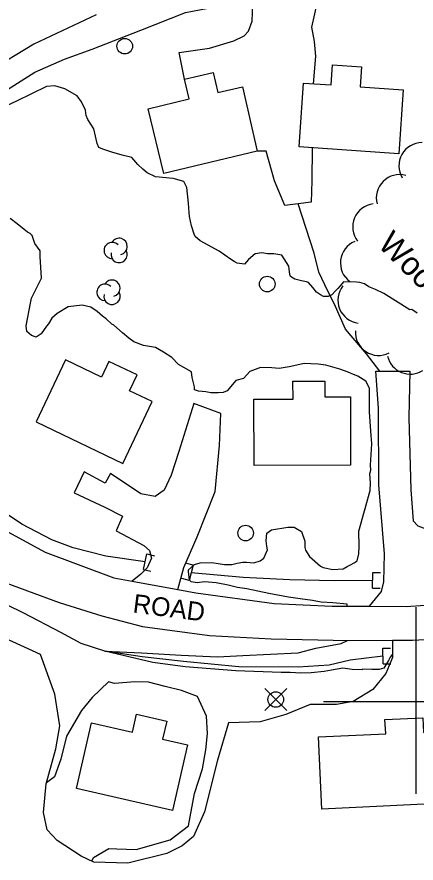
# Model space of a CAD drawing. Extents: x 642515 to 647219, y 6080136 to 6084356.
# Drawn here: x 643548.7 to 643600, y 6081979.3 to 6082088.1 of the extents above; entities that cross this region are included whole.
import ezdxf

# ---------------------------------------------------------------- set-up
doc = ezdxf.new("R2010")
doc.units = 0
for name, color, linetype in [('Level 1', 7, 'Continuous'), ('Level 19', 7, 'Continuous'), ('Level 2', 7, 'Continuous'), ('Level 21', 7, 'Continuous'), ('Level 22', 7, 'Continuous'), ('Level 26', 7, 'Continuous'), ('Level 31', 7, 'Continuous'), ('Level 36', 7, 'Continuous'), ('Level 4', 7, 'Continuous'), ('Level 44', 7, 'Continuous'), ('Level 61', 7, 'Continuous')]:
    doc.layers.add(name, color=color, linetype=linetype)

msp = doc.modelspace()

# ---------------------------------------------------------------- linework, layer by layer
at = {"layer": 'Level 1'}
msp.add_lwpolyline([(643558.37, 6081979.52), (643558.6, 6081980), (643560.55, 6081981.13), (643561.59, 6081981.11), (643564.08, 6081981), (643568.42, 6081982.26), (643570.81, 6081984.06), (643571.56, 6081988.22), (643572.59, 6081991.37), (643573.02, 6081993.85), (643573.23, 6081995.93), (643573.12, 6081998.14), (643571.94, 6082000.7), (643569.89, 6082001.46), (643567.78, 6082001.99), (643565.67, 6082002.51), (643563.9, 6082002.58), (643561.27, 6082002.36), (643560.53, 6082002.56), (643558.39, 6082000.54), (643557.04, 6081998.88), (643555.13, 6081995.61), (643554.4, 6081992.63), (643553.56, 6081990.37), (643552.52, 6081989.61)], dxfattribs=at)
at = {"layer": 'Level 19'}
for points in [[(643588.19, 6082093.13), (643587.38, 6082090.18), (643586.61, 6082086.74), (643586.95, 6082084.9), (643587.1, 6082083.01), (643586.8, 6082079.46)], [(643570.27, 6082080.03), (643569.59, 6082083.48), (643573.48, 6082084.04), (643576.63, 6082084.97), (643577.97, 6082085.61), (643578.5, 6082086.2), (643578.99, 6082087.52), (643579.07, 6082089.75), (643578.61, 6082092.74)], [(643586.69, 6082071.22), (643586.65, 6082066.97), (643586.56, 6082064.22), (643584.91, 6082064.02), (643583.19, 6082063.8), (643581.87, 6082066.97), (643580.77, 6082070.79), (643579.62, 6082070.81)], [(643594.06, 6082012.28), (643595.6, 6082014.17), (643595.89, 6082015.44), (643595.97, 6082019.03), (643595.27, 6082027.89), (643595.23, 6082037.77), (643594.88, 6082042.5), (643595.38, 6082042.5), (643599.24, 6082042.49), (643599.13, 6082036.56), (643599.38, 6082027.26), (643599.69, 6082023.25), (643600.29, 6082022.63), (643601.78, 6082022.06), (643602.53, 6082022.31), (643606.27, 6082024.68), (643612.18, 6082028.17), (643615.8, 6082030.58), (643617.11, 6082032.38), (643618.45, 6082034.47), (643620.21, 6082036.86), (643621.38, 6082039.02), (643621.98, 6082040.21)], [(643569.41, 6082014.44), (643570.18, 6082017.26), (643571.89, 6082021.22), (643574.22, 6082027.06), (643574.77, 6082032.97), (643574.94, 6082037.09), (643571.47, 6082038.36), (643569.53, 6082032.17), (643568.57, 6082029.14), (643567.67, 6082027.2), (643566.5, 6082026.41), (643564.67, 6082026.76), (643560.77, 6082029.34), (643560.07, 6082028.13), (643557.37, 6082029.56), (643556.11, 6082026.88), (643560.05, 6082025.03), (643562.29, 6082023.86), (643561.51, 6082021.97), (643565.05, 6082020.1), (643565.77, 6082019.45), (643566.03, 6082018.46), (643565.46, 6082017.22), (643564.66, 6082016.41), (643563.54, 6082015.5)], [(643597.01, 6082007.92), (643597.02, 6082005.7), (643596.17, 6082003.64), (643594.47, 6082001.58), (643591.94, 6082000.04), (643589.82, 6081999.65), (643586.44, 6081999.64), (643583.32, 6081998.39), (643579.99, 6081997.41), (643575.93, 6081997.32), (643574.51, 6081992.5), (643572.83, 6081985.86), (643571.44, 6081982.69), (643569.98, 6081981.49), (643568.02, 6081980.5), (643563.01, 6081979.27), (643558.61, 6081979.41), (643557, 6081980.17), (643553.9, 6081982.18), (643552.61, 6081983.56), (643552.16, 6081985.78), (643552.48, 6081989.46), (643553.75, 6081993.95), (643554.26, 6081996.91), (643553.63, 6082000.98), (643551.76, 6082006.07), (643543.57, 6082009.83)]]:
    msp.add_lwpolyline(points, dxfattribs=at)
at = {"layer": 'Level 2'}
for points in [[(643552.53, 6082079.09), (643548.68, 6082077.22), (643547.39, 6082076.63), (643545.2, 6082075.4), (643544.2, 6082075.14), (643543.39, 6082074.58), (643540.62, 6082072.8), (643539.44, 6082072.66), (643540.36, 6082074.19), (643542.27, 6082076.96), (643543.27, 6082077.89), (643544.92, 6082079.46), (643545.23, 6082079.63), (643545.86, 6082081.5)], [(643600.17, 6082049.97), (643599.5, 6082050.42), (643599.26, 6082050.4), (643595.89, 6082052.5), (643594.82, 6082053), (643593.99, 6082053.35), (643593.41, 6082053.72), (643592.83, 6082053.93), (643592.39, 6082053.95), (643590.74, 6082053.98), (643590.55, 6082053.77), (643590.28, 6082053.48), (643589.98, 6082053.14), (643589.71, 6082052.85), (643589.22, 6082052.31), (643588.74, 6082052.12), (643588.14, 6082052.13), (643587.77, 6082052.31), (643587.26, 6082052.68), (643586.79, 6082053.25), (643586.23, 6082053.9), (643585.95, 6082054.01), (643585.3, 6082054.13), (643584.48, 6082054.33), (643584.23, 6082054.48), (643583.9, 6082054.7), (643583.8, 6082054.93), (643583.71, 6082056), (643582.79, 6082057.43), (643581.77, 6082057.58), (643580.97, 6082057.61), (643580.24, 6082057.73), (643579.36, 6082057.61), (643578.51, 6082056.85), (643577.98, 6082056.26), (643577.04, 6082056.41), (643576.67, 6082056.59), (643576.21, 6082056.92), (643574.75, 6082057.92), (643572.3, 6082059.27), (643571.67, 6082059.84), (643571.54, 6082060.11), (643571.16, 6082061.2), (643570.93, 6082062.39), (643570.86, 6082062.9), (643570.8, 6082064.1), (643570.57, 6082066.12), (643570.21, 6082066.9), (643568.82, 6082067.3), (643566.55, 6082067.5), (643565.48, 6082068.01), (643564.93, 6082068.5), (643564.3, 6082069.06), (643563.52, 6082069.98), (643562.26, 6082070.27), (643560.95, 6082070.68), (643559.76, 6082071.06), (643559.27, 6082071.27), (643559.04, 6082071.78), (643558.83, 6082072.72), (643558.62, 6082073.67), (643557.87, 6082074.87), (643557.64, 6082075.37), (643557.57, 6082076.05), (643557.02, 6082077.14), (643556.5, 6082077.91), (643554.88, 6082078.82), (643553.61, 6082079.19), (643552.53, 6082079.09)], [(643584.7, 6082043.29), (643583.75, 6082043.08), (643582.47, 6082042.86), (643581.5, 6082042.96), (643580.06, 6082042.97), (643578.68, 6082042.46), (643577.88, 6082041.58), (643576.89, 6082041.33), (643575.75, 6082039.99), (643575.24, 6082039.77), (643574.6, 6082039.73), (643574.12, 6082039.71), (643573.68, 6082039.73), (643573.03, 6082039.85), (643572.06, 6082039.96), (643571.57, 6082040.09), (643571.55, 6082040.49), (643571.28, 6082041.71), (643571.16, 6082042.42), (643570.21, 6082042.97), (643569.51, 6082043.37), (643568.65, 6082044.28), (643567.57, 6082044.94), (643566.54, 6082045.56), (643565, 6082045.8), (643563.76, 6082046.29), (643563.14, 6082046.77), (643562.3, 6082047.44), (643561.2, 6082048.42), (643560.95, 6082048.57), (643560.19, 6082049.24), (643559.73, 6082049.58), (643559.06, 6082050.18), (643558.26, 6082050.73), (643557.13, 6082050.99), (643555.33, 6082050.78), (643553.93, 6082049.91), (643553.24, 6082049.32), (643552.79, 6082048.58), (643552.53, 6082048.28), (643551.86, 6082047.29), (643551.19, 6082046.9), (643550.62, 6082047.11), (643549.99, 6082047.59), (643549.91, 6082048.34), (643550.48, 6082051.24), (643550.61, 6082051.88), (643551.88, 6082054.46), (643551.73, 6082057.24), (643551.73, 6082057.99), (643551.04, 6082058.91), (643550.7, 6082059.97), (643550.45, 6082060.2), (643550.08, 6082060.38), (643548.77, 6082061.46), (643547.85, 6082062.13)], [(643591.21, 6082012.3), (643591.18, 6082012.57), (643589.36, 6082012.75), (643587.83, 6082012.83), (643586.73, 6082013.05), (643585.15, 6082013.24), (643583.66, 6082013.44), (643581.14, 6082013.95), (643579.72, 6082014.23), (643578.3, 6082014.51), (643577.09, 6082014.69), (643575.9, 6082014.98), (643574.36, 6082015.3), (643572.87, 6082015.42), (643571.91, 6082015.29), (643571.14, 6082015.45), (643570.93, 6082015.63), (643570.79, 6082016.74), (643570.78, 6082016.98), (643571.55, 6082017.65), (643572.3, 6082017.89), (643573.78, 6082017.93), (643575.44, 6082017.66), (643576.37, 6082017.67), (643577.04, 6082017.82), (643577.76, 6082017.94), (643578.24, 6082017.97), (643579.21, 6082017.86), (643580, 6082018.14), (643580.46, 6082018.48), (643580.97, 6082019.54), (643580.86, 6082020.01), (643580.79, 6082020.69), (643580.85, 6082021.68), (643581.47, 6082022.12), (643583.55, 6082022.46), (643584.39, 6082022.47), (643585.3, 6082021.88), (643585.73, 6082020.67), (643585.73, 6082019.83), (643585.83, 6082019.52), (643586.36, 6082018.67), (643587.75, 6082017.43), (643588.12, 6082017.26), (643589.34, 6082017), (643590.66, 6082017.11), (643591.2, 6082017.38), (643591.63, 6082017.6), (643592.1, 6082017.86), (643592.49, 6082018.12), (643592.68, 6082019.01), (643592.75, 6082020.01), (643592.69, 6082021.95), (643594.15, 6082027.16), (643594.21, 6082028.16), (643594.11, 6082029.3), (643594.25, 6082029.79), (643594.21, 6082030.42), (643594.35, 6082033.18), (643594.23, 6082034.8), (643594.06, 6082037.3), (643594.06, 6082040.32), (643593.57, 6082041.21), (643592.57, 6082041.88), (643592, 6082042.08), (643591.3, 6082042.4), (643590.23, 6082042.75), (643589.33, 6082043.02), (643588.44, 6082043.29), (643587.47, 6082043.4), (643586.54, 6082043.47), (643585.65, 6082043.5), (643584.7, 6082043.29)], [(643597.02, 6082006.12), (643596.71, 6082005.73), (643596.49, 6082005.32), (643595.9, 6082004.33), (643595.3, 6082004.18), (643594.38, 6082004.17), (643593.17, 6082004.19), (643593.1, 6082004.11), (643591.85, 6082004.16), (643590.64, 6082004.34), (643589.16, 6082004.06), (643588.25, 6082003.89), (643586.57, 6082003.72), (643585.25, 6082003.69), (643583.88, 6082003.78), (643582.71, 6082003.76), (643576.88, 6082003.97), (643570.35, 6082004.5), (643566.22, 6082005.07), (643560.04, 6082006.51), (643564.75, 6082006.32), (643569.87, 6082006), (643574.54, 6082005.77), (643577.79, 6082005.98), (643584.88, 6082006.31), (643587.17, 6082006.91), (643590.44, 6082007.48), (643591.24, 6082007.88)]]:
    msp.add_lwpolyline(points, dxfattribs=at)
at = {"layer": 'Level 21'}
for points in [[(643558.93, 6082088.3), (643550.89, 6082084.56), (643545.1, 6082081.03)], [(643547.58, 6082021.86), (643552.37, 6082019.25), (643561.19, 6082015.93), (643563.54, 6082015.5), (643569.41, 6082014.44), (643571.75, 6082014.02), (643581.8, 6082012.65), (643589.25, 6082012.31), (643594.06, 6082012.28), (643598.78, 6082012.24), (643601.23, 6082012.43)], [(643545.63, 6082015.92), (643554.17, 6082012.78), (643559.67, 6082011.05), (643564.87, 6082009.67), (643573.49, 6082008.51), (643581.43, 6082008.12), (643591.41, 6082007.87), (643597.01, 6082007.92), (643599.6, 6082007.94), (643605.23, 6082008.23)]]:
    msp.add_lwpolyline(points, dxfattribs=at)
at = {"layer": 'Level 22'}
msp.add_lwpolyline([(643595.38, 6082042.5), (643593.69, 6082044.76), (643590.99, 6082047.93), (643589.53, 6082051.2), (643588.69, 6082052.79), (643587.55, 6082055.24), (643586.94, 6082057.68), (643584.91, 6082064.02)], dxfattribs=at)
at = {"layer": 'Level 26'}
for p, q in [((643564.99, 6082017.03), (643565.43, 6082019.01)), ((643565.43, 6082019.01), (643566.41, 6082018.79)), ((643564.99, 6082017.03), (643565.97, 6082016.81)), ((643571.38, 6082017.55), (643570.42, 6082017.81)), ((643571.38, 6082017.55), (643570.88, 6082015.61)), ((643570.88, 6082015.61), (643569.92, 6082015.85)), ((643594.44, 6082014.62), (643594.48, 6082016.64)), ((643594.48, 6082016.64), (643595.48, 6082016.62)), ((643594.44, 6082014.62), (643595.44, 6082014.6)), ((643595.76, 6082006.89), (643596.76, 6082006.91)), ((643595.8, 6082004.87), (643595.76, 6082006.89)), ((643595.8, 6082004.87), (643596.8, 6082004.89))]:
    msp.add_line(p, q, dxfattribs=at)
at = {"layer": 'Level 31'}
for points in [[(643597.84, 6082070.45), (643585.01, 6082071.33), (643585.58, 6082079.54), (643589.12, 6082079.3), (643589.3, 6082081.91), (643593.02, 6082081.65), (643592.84, 6082079.07), (643598.37, 6082078.69), (643597.84, 6082070.45)], [(643579.62, 6082070.81), (643567.62, 6082067.91), (643565.61, 6082076.24), (643570.88, 6082077.52), (643570.27, 6082080.03), (643573.95, 6082080.92), (643574.58, 6082078.32), (643577.73, 6082079.08), (643579.62, 6082070.81)], [(643563.22, 6082039.98), (643564.2, 6082042.02), (643560.56, 6082043.76), (643559.6, 6082041.76), (643555, 6082043.96), (643551.19, 6082035.99), (643562.34, 6082030.66), (643566.13, 6082038.59), (643563.22, 6082039.98)], [(643591.61, 6082030.42), (643579.22, 6082030.38), (643579.19, 6082038.9), (643584.23, 6082038.92), (643584.22, 6082041.21), (643588.31, 6082041.22), (643588.31, 6082039.19), (643591.63, 6082039.2), (643591.61, 6082030.42)], [(643615.11, 6081987.55), (643587.95, 6081986.22), (643587.5, 6081995.49), (643596.14, 6081995.91), (643596.05, 6081997.71), (643600.93, 6081997.95), (643601.02, 6081996.08), (643606.72, 6081996.36), (643606.62, 6081998.26), (643611.34, 6081998.49), (643611.43, 6081996.64), (643614.72, 6081996.8), (643615.11, 6081987.55)], [(643570.66, 6081994.47), (643568.72, 6081986.03), (643556.39, 6081988.85), (643558.32, 6081997.29), (643563.58, 6081996.09), (643564.11, 6081998.41), (643567.99, 6081997.53), (643567.46, 6081995.19), (643570.66, 6081994.47)]]:
    msp.add_lwpolyline(points, dxfattribs=at)
at = {"layer": 'Level 36'}
for p, q in [((643583.42, 6081998.89), (643580.6, 6082001.71)), ((643580.6, 6081998.89), (643583.42, 6082001.71))]:
    msp.add_line(p, q, dxfattribs=at)
for centre in [(643562.6, 6082084.29), (643580.92, 6082053.71), (643578.14, 6082021.7), (643582.01, 6082000.3)]:
    msp.add_circle(centre, 1, dxfattribs=at)
at = {"layer": 'Level 4'}
for points in [[(643526.43, 6082037.47), (643521.14, 6082040.98), (643518.78, 6082042.55), (643517.96, 6082043.51), (643517.75, 6082044.39), (643518.06, 6082046.1), (643519.15, 6082048.17), (643521.07, 6082050.57), (643524.53, 6082056.39), (643528.11, 6082060.81), (643532.77, 6082066.18), (643536.28, 6082069.83), (643539.44, 6082072.66), (643543.44, 6082075.5), (643546.57, 6082078.12), (643551.02, 6082080.94), (643554.85, 6082082.64), (643558.39, 6082083.91), (643564.65, 6082086.34), (643570.39, 6082088.62), (643574, 6082089.3), (643577.08, 6082089.79)], [(643565.21, 6082018.01), (643560.16, 6082018.71), (643555.98, 6082019.79), (643553.22, 6082020.81), (643549.35, 6082022.83), (643545.94, 6082025.11), (643539.87, 6082028.86), (643534.05, 6082032.47), (643531.59, 6082034.07)], [(643595.78, 6082005.87), (643591.56, 6082005.37), (643588.89, 6082004.71), (643584.91, 6082004.46), (643577.28, 6082004.51), (643570.13, 6082005.18), (643564.85, 6082005.79), (643560.04, 6082006.51), (643557, 6082007.48), (643554.38, 6082008.91), (643549.63, 6082011.41), (643542.95, 6082014.64), (643538.48, 6082016.51), (643535.76, 6082017.53)], [(643594.46, 6082015.62), (643589.58, 6082015.57), (643583.84, 6082015.67), (643577.8, 6082015.97), (643574.47, 6082016.28), (643571.14, 6082016.59)]]:
    msp.add_lwpolyline(points, dxfattribs=at)
at = {"layer": 'Level 44'}
for centre, radius, start, end in [((643600.84, 6082068.89), 3, 90.4034, 210.3814), ((643597.93, 6082064.78), 3, 74.7961, 194.774), ((643594.9, 6082061.04), 3, 97.2369, 217.2148), ((643561.88, 6082058.55), 1.05, 282.2692, 149.7263), ((643560.98, 6082058.02), 1.05, 44.1154, 269.804), ((643593.33, 6082056.42), 3, 112.8589, 232.8368), ((643561.88, 6082057.5), 1.05, 166.9369, 29.6212), ((643560.96, 6082053.18), 1.05, 282.2692, 149.7263), ((643560.06, 6082052.65), 1.05, 44.1154, 269.804), ((643593, 6082051.65), 3, 142.2131, 262.1911), ((643560.96, 6082052.13), 1.05, 166.9369, 29.6212), ((643595.24, 6082047.53), 3, 176.6951, 296.673), ((643599.3, 6082045.13), 3, 193.5201, 302.344)]:
    msp.add_arc(centre, radius, start, end, dxfattribs=at)
at = {"layer": 'Level 61'}
for p, q in [((643600, 6082012.16), (643600, 6081988.16)), ((643612.16, 6082000), (643588.16, 6082000))]:
    msp.add_line(p, q, dxfattribs=at)

# ---------------------------------------------------------------- texts
at = {"layer": 'Level 21'}
msp.add_text('ROAD', height=2.4, rotation=352.7116, dxfattribs=at).set_placement((643563.55, 6082011.5))
at = {"layer": 'Level 44'}
msp.add_text('Wood', height=3, rotation=315.1749, dxfattribs=at).set_placement((643594.99, 6082058.65))

doc.saveas('drawing.dxf')
